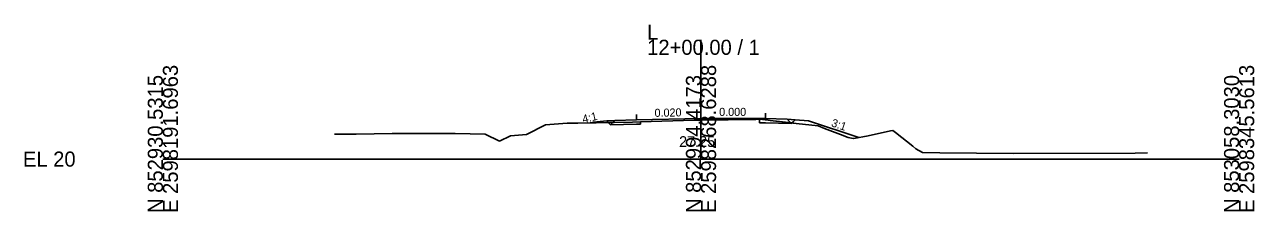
# Model space of a CAD drawing. Extents: x -26 to 1203, y -10 to 9526.
# Drawn here: x -25.7 to 202.8, y 1990.3 to 2024.9 of the extents above; entities that cross this region are included whole.
import ezdxf

# ---------------------------------------------------------------- set-up
doc = ezdxf.new("R2010")
doc.units = 0
for name, color, linetype in [('Exist Cross Section Cell', 7, 'Continuous'), ('Exist XS Center Line Elevation Label', 7, 'Continuous'), ('Exist XS Ground Line', 7, 'Continuous'), ('Prop XS Earthwork Shape', 7, 'Continuous'), ('Prop XS EOT Tick Mark', 7, 'Continuous'), ('Prop XS Finish Grade', 7, 'Continuous'), ('Prop XS Finish Grade Earthwork', 7, 'Continuous'), ('Prop XS Finish Grade Paved Shoulder', 7, 'Continuous'), ('Prop XS Finish Grade Pavement', 7, 'Continuous'), ('Prop XS Pvmt Edge Slope', 7, 'Continuous'), ('Prop XS SE Text', 7, 'Continuous'), ('Prop XS Side Slope Text', 7, 'Continuous'), ('Prop XS Subgrade Earthwork', 7, 'Continuous')]:
    doc.layers.add(name, color=color, linetype=linetype)

msp = doc.modelspace()

# ---------------------------------------------------------------- linework, layer by layer
at = {"layer": 'Exist Cross Section Cell'}
for p, q in [((100, 2000), (100, 2022.14)), ((0, 2000), (100, 2000)), ((100, 2000), (200, 2000))]:
    msp.add_line(p, q, dxfattribs=at)
at = {"layer": 'Exist XS Ground Line'}
for p, q in [((71.12, 2006.33), (75.12, 2006.65)), ((75.12, 2006.65), (77.12, 2006.69)), ((77.12, 2006.69), (87.26, 2006.88)), ((87.26, 2006.88), (88.75, 2006.89)), ((88.75, 2006.89), (98.76, 2007.21)), ((98.76, 2007.21), (99.98, 2007.25)), ((99.98, 2007.25), (110.19, 2007.37)), ((110.19, 2007.37), (110.9, 2007.38)), ((110.9, 2007.38), (112.47, 2007.2)), ((112.47, 2007.2), (112.87, 2007.16)), ((112.87, 2007.16), (117.69, 2006.61)), ((117.69, 2006.61), (121.76, 2006.17)), ((31.91, 2004.63), (35.95, 2004.65)), ((35.95, 2004.65), (42.59, 2004.77)), ((42.59, 2004.77), (54.3, 2004.72)), ((54.3, 2004.72), (59.91, 2004.63)), ((59.91, 2004.63), (62.56, 2003.3)), ((62.56, 2003.3), (64.59, 2004.31)), ((64.59, 2004.31), (67.59, 2004.56)), ((67.59, 2004.56), (71.12, 2006.33)), ((121.76, 2006.17), (122.95, 2005.69)), ((122.95, 2005.69), (125.9, 2004.58)), ((125.9, 2004.58), (127.34, 2004)), ((128.39, 2003.8), (131.09, 2004.31)), ((131.09, 2004.31), (135.19, 2005.23)), ((135.19, 2005.23), (135.64, 2005.33)), ((135.64, 2005.33), (136.16, 2004.95)), ((136.16, 2004.95), (139.36, 2002.43)), ((127.34, 2004), (127.95, 2003.89)), ((127.95, 2003.89), (128.39, 2003.8)), ((139.36, 2002.43), (139.92, 2001.92)), ((139.92, 2001.92), (141.17, 2001.22)), ((141.17, 2001.22), (144.39, 2001.19)), ((144.39, 2001.19), (157.99, 2001.06)), ((157.99, 2001.06), (180.68, 2001.12)), ((180.68, 2001.12), (182.96, 2001.14))]:
    msp.add_line(p, q, dxfattribs=at)
at = {"layer": 'Prop XS Earthwork Shape'}
for points in [[(82.5, 2007.07), (80, 2006.87), (79.46, 2006.73), (82.78, 2006.79)], [(83.19, 2006.38), (82.78, 2006.79), (87.26, 2006.88), (88.75, 2006.89), (88.75, 2006.49), (88, 2006.48)], [(110.9, 2006.72), (110.9, 2007.38), (112.47, 2007.2), (112.87, 2007.16), (116.89, 2006.7), (116.81, 2006.62), (112, 2006.72)], [(120, 2007.11), (129.36, 2003.99), (128.39, 2003.8), (127.95, 2003.89), (127.34, 2004), (125.9, 2004.58), (122.95, 2005.69), (121.76, 2006.17), (117.69, 2006.61), (116.89, 2006.7), (117.5, 2007.31)]]:
    msp.add_lwpolyline(points, close=True, dxfattribs=at)
at = {"layer": 'Prop XS EOT Tick Mark'}
for p, q in [((88, 2007.27), (88, 2008.27)), ((112, 2007.51), (112, 2008.51))]:
    msp.add_line(p, q, dxfattribs=at)
at = {"layer": 'Prop XS Finish Grade'}
for p, q in [((84, 2007.19), (82.5, 2007.07)), ((116, 2007.43), (117.5, 2007.31))]:
    msp.add_line(p, q, dxfattribs=at)
at = {"layer": 'Prop XS Finish Grade Earthwork'}
for p, q in [((80, 2006.87), (79.46, 2006.73)), ((82.5, 2007.07), (80, 2006.87)), ((117.5, 2007.31), (120, 2007.11)), ((120, 2007.11), (129.36, 2003.99))]:
    msp.add_line(p, q, dxfattribs=at)
at = {"layer": 'Prop XS Finish Grade Paved Shoulder'}
for p, q in [((88, 2007.27), (84, 2007.19)), ((112, 2007.51), (116, 2007.43))]:
    msp.add_line(p, q, dxfattribs=at)
at = {"layer": 'Prop XS Finish Grade Pavement'}
for p, q in [((88, 2007.27), (100, 2007.51)), ((100, 2007.51), (112, 2007.51))]:
    msp.add_line(p, q, dxfattribs=at)
at = {"layer": 'Prop XS Pvmt Edge Slope'}
for p, q in [((84, 2007.19), (83.19, 2006.38)), ((116, 2007.43), (116.81, 2006.62))]:
    msp.add_line(p, q, dxfattribs=at)
at = {"layer": 'Prop XS Subgrade Earthwork'}
for p, q in [((83.19, 2006.38), (82.5, 2007.07)), ((88.75, 2006.49), (88.75, 2006.89)), ((110.9, 2006.72), (110.9, 2007.38)), ((110.9, 2006.72), (112, 2006.72)), ((112, 2006.72), (116.81, 2006.62)), ((116.81, 2006.62), (117.5, 2007.31)), ((88, 2006.48), (83.19, 2006.38)), ((88.75, 2006.49), (88, 2006.48))]:
    msp.add_line(p, q, dxfattribs=at)

# ---------------------------------------------------------------- texts
at = {"layer": 'Exist Cross Section Cell'}
for s, p in [('L', (90, 2022.14)), ('12+00.00 / 1', (90, 2019.34)), ('EL 20', (-26, 1998.6))]:
    msp.add_text(s, height=2.8, dxfattribs=at).set_placement(p)
for s, p in [('E 2598191.6963', (2.8, 1990)), ('E 2598268.6288', (102.8, 1990)), ('E 2598345.5613', (202.8, 1990)), ('N 852930.5315', (0, 1990)), ('N 852994.4173', (100, 1990)), ('N 853058.3030', (200, 1990))]:
    msp.add_text(s, height=2.8, rotation=90, dxfattribs=at).set_placement(p)
at = {"layer": 'Exist XS Center Line Elevation Label'}
msp.add_text('27.25', height=2, dxfattribs=at).set_placement((95.93, 2002.25))
at = {"layer": 'Prop XS SE Text'}
for s, rotation, p in [('0.020', 1.1458, (91.38, 2007.83)), ('0.000', 360, (103.38, 2008.01))]:
    msp.add_text(s, height=1.5, rotation=rotation, dxfattribs=at).set_placement(p)
at = {"layer": 'Prop XS Side Slope Text'}
for s, rotation, p in [('4:1', 13.2903, (78.13, 2006.66)), ('3:1', 341.5651, (124.1, 2006.11))]:
    msp.add_text(s, height=1.5, rotation=rotation, dxfattribs=at).set_placement(p)

doc.saveas('drawing.dxf')
